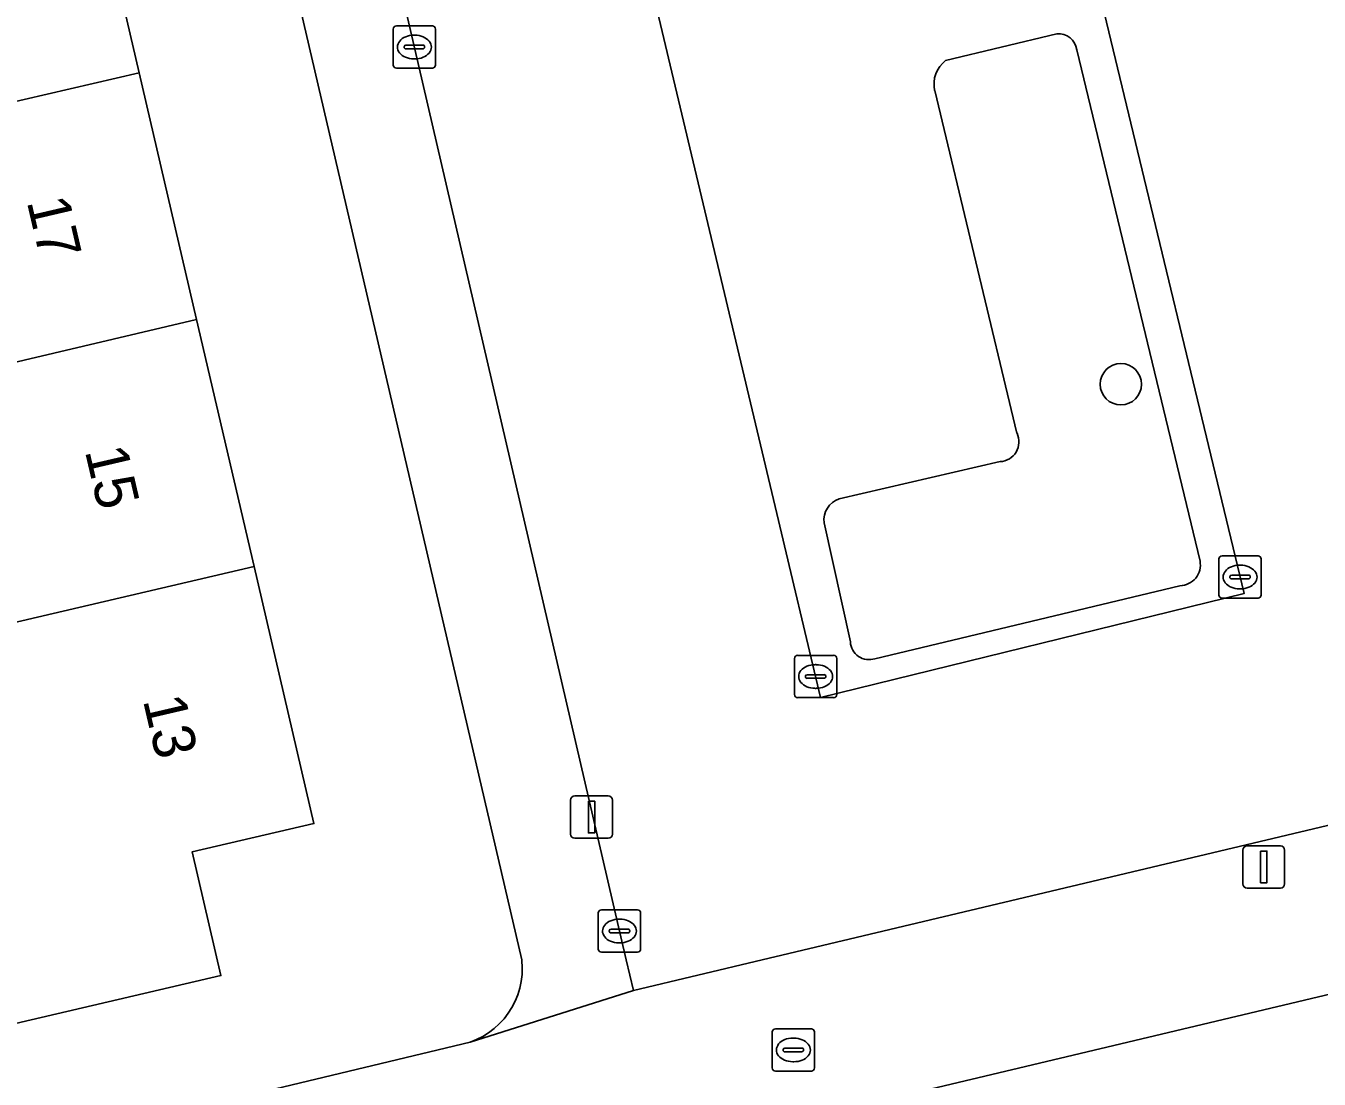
# Model space of a CAD drawing. Extents: x 158031 to 159244, y 380104 to 381214.
# Drawn here: x 158511.52 to 158542.1, y 380747.18 to 380772.08 of the extents above; entities that cross this region are included whole.
import ezdxf

# ---------------------------------------------------------------- set-up
doc = ezdxf.new("R2010")
doc.units = 0
for name, color, linetype in [('IMGEO_Boom', 7, 'Continuous'), ('IMGEO_Erf', 7, 'Continuous'), ('IMGEO_Groenvoorziening', 7, 'Continuous'), ('IMGEO_Kolk', 7, 'Continuous'), ('IMGEO_Lichtmast', 7, 'Continuous'), ('IMGEO_Pand', 7, 'Continuous'), ('IMGEO_Pand_nummerreeks', 7, 'Continuous'), ('IMGEO_Parkeervlak_open', 7, 'Continuous'), ('IMGEO_Rijbaan_lokaal_open', 7, 'Continuous'), ('IMGEO_Rioolput', 7, 'Continuous'), ('IMGEO_Voetpad_open', 7, 'Continuous')]:
    doc.layers.add(name, color=color, linetype=linetype)

msp = doc.modelspace()

# ---------------------------------------------------------------- linework, layer by layer
at = {"layer": 'IMGEO_Boom'}
msp.add_circle((158537.411, 380763.609), 0.489, dxfattribs=at)
at = {"layer": 'IMGEO_Erf'}
for points in [[(158513.376, 380745.986), (158522.019, 380748.055), (158522.172, 380748.116), (158522.319, 380748.19), (158522.458, 380748.277), (158522.589, 380748.376), (158522.711, 380748.487), (158522.823, 380748.607), (158522.923, 380748.738), (158523.011, 380748.877), (158523.087, 380749.023), (158523.149, 380749.175), (158523.197, 380749.332), (158523.231, 380749.493), (158523.251, 380749.657), (158523.255, 380749.821), (158523.246, 380749.985), (158523.244, 380750), (158511.631, 380799.863)], [(158511.474, 380782.644), (158512.835, 380776.803), (158514.193, 380770.97), (158515.552, 380765.137), (158516.911, 380759.304), (158518.328, 380753.222), (158515.445, 380752.551), (158516.126, 380749.629), (158505.929, 380747.254)], [(158545.767, 380750), (158515.725, 380742.86), (158520.628, 380722.152), (158526.203, 380723.472), (158552.37, 380729.668)]]:
    msp.add_lwpolyline(points, dxfattribs=at)
at = {"layer": 'IMGEO_Groenvoorziening'}
for points in [[(158535.895, 380771.89), (158533.268, 380771.262)], [(158539.283, 380759.427), (158536.368, 380771.514)], [(158533.008, 380770.554), (158534.955, 380762.449)], [(158534.556, 380761.78), (158530.749, 380760.899)], [(158530.392, 380760.331), (158531.015, 380757.519)], [(158531.595, 380757.121), (158538.808, 380758.847)]]:
    msp.add_lwpolyline(points, dxfattribs=at)
for centre, radius, start, end in [((158535.941, 380771.463), 0.43, 6.8369, 96.1989), ((158533.689, 380770.706), 0.698, 127.1097, 192.5607), ((158534.533, 380762.247), 0.468, 272.8147, 25.5605), ((158530.922, 380760.394), 0.534, 108.9016, 186.7979), ((158538.803, 380759.336), 0.489, 270.5911, 10.7764), ((158531.456, 380757.54), 0.441, 182.7007, 288.3829)]:
    msp.add_arc(centre, radius, start, end, dxfattribs=at)
at = {"layer": 'IMGEO_Kolk'}
for p, q in [((158520.203, 380771.155), (158520.203, 380772.007)), ((158520.278, 380772.081), (158521.13, 380772.081)), ((158521.204, 380772.007), (158521.204, 380771.155)), ((158520.505, 380771.624), (158520.903, 380771.624)), ((158520.691, 380771.861), (158520.716, 380771.861)), ((158520.462, 380771.575), (158520.462, 380771.587)), ((158520.9, 380771.538), (158520.502, 380771.538)), ((158520.946, 380771.587), (158520.946, 380771.575)), ((158521.13, 380771.081), (158520.278, 380771.081)), ((158520.714, 380771.301), (158520.689, 380771.301)), ((158539.73, 380758.626), (158539.73, 380759.478)), ((158539.805, 380759.552), (158540.657, 380759.552)), ((158540.731, 380759.478), (158540.731, 380758.626)), ((158540.032, 380759.095), (158540.43, 380759.095)), ((158540.218, 380759.332), (158540.243, 380759.332)), ((158539.989, 380759.046), (158539.989, 380759.058)), ((158540.427, 380759.009), (158540.029, 380759.009)), ((158540.241, 380758.772), (158540.216, 380758.772)), ((158540.473, 380759.058), (158540.473, 380759.046)), ((158540.657, 380758.552), (158539.805, 380758.552)), ((158529.692, 380756.274), (158529.692, 380757.126)), ((158529.767, 380757.2), (158530.619, 380757.2)), ((158530.18, 380756.98), (158530.205, 380756.98)), ((158530.693, 380757.126), (158530.693, 380756.274)), ((158529.951, 380756.694), (158529.951, 380756.706)), ((158530.389, 380756.657), (158529.991, 380756.657)), ((158529.994, 380756.743), (158530.392, 380756.743)), ((158530.435, 380756.706), (158530.435, 380756.694)), ((158530.203, 380756.42), (158530.178, 380756.42)), ((158530.619, 380756.2), (158529.767, 380756.2)), ((158525.128, 380751.183), (158525.98, 380751.183)), ((158525.053, 380750.257), (158525.053, 380751.109)), ((158525.541, 380750.963), (158525.566, 380750.963)), ((158526.054, 380751.109), (158526.054, 380750.257)), ((158525.312, 380750.677), (158525.312, 380750.689)), ((158525.75, 380750.64), (158525.352, 380750.64)), ((158525.355, 380750.726), (158525.753, 380750.726)), ((158525.796, 380750.689), (158525.796, 380750.677)), ((158525.564, 380750.403), (158525.539, 380750.403)), ((158525.98, 380750.183), (158525.128, 380750.183))]:
    msp.add_line(p, q, dxfattribs=at)
for points in [[(158520.203, 380771.155), (158520.203, 380772.007)], [(158520.278, 380772.081), (158521.13, 380772.081)], [(158521.204, 380772.007), (158521.204, 380771.155)], [(158521.13, 380771.081), (158520.278, 380771.081)], [(158539.73, 380758.626), (158539.73, 380759.478)], [(158539.805, 380759.552), (158540.657, 380759.552)], [(158540.731, 380759.478), (158540.731, 380758.626)], [(158540.657, 380758.552), (158539.805, 380758.552)], [(158529.692, 380756.274), (158529.692, 380757.126)], [(158529.767, 380757.2), (158530.619, 380757.2)], [(158530.693, 380757.126), (158530.693, 380756.274)], [(158530.619, 380756.2), (158529.767, 380756.2)], [(158525.128, 380751.183), (158525.98, 380751.183)], [(158525.053, 380750.257), (158525.053, 380751.109)], [(158526.054, 380751.109), (158526.054, 380750.257)], [(158525.98, 380750.183), (158525.128, 380750.183)]]:
    msp.add_lwpolyline(points, dxfattribs=at)
for centre, radius, start, end in [((158520.28, 380772.005), 0.0765, 91.552, 178.448), ((158520.28, 380772.005), 0.0765, 91.552, 178.448), ((158521.128, 380772.005), 0.0765, 1.552, 88.448), ((158521.128, 380772.005), 0.0765, 1.552, 88.448), ((158520.502, 380771.584), 0.0403, 85.8775, 175.7526), ((158520.907, 380771.586), 0.0386, 1.7309, 96.639), ((158520.499, 380771.574), 0.0366, 178.938, 274.7102), ((158520.903, 380771.581), 0.043, 264.8664, 352.4533), ((158520.28, 380771.157), 0.0765, 181.552, 268.448), ((158520.28, 380771.157), 0.0765, 181.552, 268.448), ((158521.128, 380771.157), 0.0765, 271.552, 358.448), ((158521.128, 380771.157), 0.0765, 271.552, 358.448), ((158539.807, 380759.476), 0.0765, 91.552, 178.448), ((158539.807, 380759.476), 0.0765, 91.552, 178.448), ((158540.655, 380759.476), 0.0765, 1.552, 88.448), ((158540.655, 380759.476), 0.0765, 1.552, 88.448), ((158540.029, 380759.055), 0.0403, 85.8775, 175.7526), ((158540.434, 380759.057), 0.0386, 1.7309, 96.639), ((158540.026, 380759.045), 0.0366, 178.938, 274.7102), ((158540.43, 380759.052), 0.043, 264.8664, 352.4533), ((158539.807, 380758.628), 0.0765, 181.552, 268.448), ((158539.807, 380758.628), 0.0765, 181.552, 268.448), ((158540.655, 380758.628), 0.0765, 271.552, 358.448), ((158540.655, 380758.628), 0.0765, 271.552, 358.448), ((158529.769, 380757.124), 0.0765, 91.552, 178.448), ((158529.769, 380757.124), 0.0765, 91.552, 178.448), ((158530.617, 380757.124), 0.0765, 1.552, 88.448), ((158530.617, 380757.124), 0.0765, 1.552, 88.448), ((158529.991, 380756.703), 0.0403, 85.8775, 175.7526), ((158529.988, 380756.693), 0.0366, 178.938, 274.7102), ((158530.392, 380756.7), 0.043, 264.8664, 352.4533), ((158530.396, 380756.705), 0.0386, 1.7309, 96.639), ((158529.769, 380756.276), 0.0765, 181.552, 268.448), ((158529.769, 380756.276), 0.0765, 181.552, 268.448), ((158530.617, 380756.276), 0.0765, 271.552, 358.448), ((158530.617, 380756.276), 0.0765, 271.552, 358.448), ((158525.13, 380751.107), 0.0765, 91.552, 178.448), ((158525.13, 380751.107), 0.0765, 91.552, 178.448), ((158525.978, 380751.107), 0.0765, 1.552, 88.448), ((158525.978, 380751.107), 0.0765, 1.552, 88.448), ((158525.352, 380750.686), 0.0403, 85.8775, 175.7526), ((158525.349, 380750.676), 0.0366, 178.938, 274.7102), ((158525.753, 380750.683), 0.043, 264.8664, 352.4533), ((158525.757, 380750.688), 0.0386, 1.7309, 96.639), ((158525.13, 380750.259), 0.0765, 181.552, 268.448), ((158525.13, 380750.259), 0.0765, 181.552, 268.448), ((158525.978, 380750.259), 0.0765, 271.552, 358.448), ((158525.978, 380750.259), 0.0765, 271.552, 358.448)]:
    msp.add_arc(centre, radius, start, end, dxfattribs=at)
for centre, major_axis, ratio, start_param, end_param in [((158520.69, 380771.581), (-0.387, 0.002), 0.722429, 4.712389, 7.853982), ((158520.715, 380771.581), (-0.39, 0.002), 0.717154, 1.570796, 4.712389), ((158540.217, 380759.052), (-0.387, 0.002), 0.722429, 4.712389, 7.853982), ((158540.242, 380759.052), (-0.39, 0.002), 0.717154, 1.570796, 4.712389), ((158530.179, 380756.7), (-0.387, 0.002), 0.722429, 4.712389, 7.853982), ((158530.204, 380756.7), (-0.39, 0.002), 0.717154, 1.570796, 4.712389), ((158525.54, 380750.683), (-0.387, 0.002), 0.722429, 4.712389, 7.853982), ((158525.565, 380750.683), (-0.39, 0.002), 0.717154, 1.570796, 4.712389)]:
    msp.add_ellipse(centre, major_axis=major_axis, ratio=ratio, start_param=start_param, end_param=end_param, dxfattribs=at)
at = {"layer": 'IMGEO_Lichtmast'}
for p, q in [((158524.498, 380753.876), (158525.288, 380753.876)), ((158525.288, 380753.876), (158524.498, 380753.876)), ((158524.398, 380752.976), (158524.398, 380753.776)), ((158524.398, 380753.776), (158524.398, 380752.976)), ((158525.388, 380753.776), (158525.388, 380752.976)), ((158525.388, 380752.976), (158525.388, 380753.776)), ((158525.288, 380752.876), (158524.498, 380752.876)), ((158524.498, 380752.876), (158525.288, 380752.876)), ((158540.395, 380752.698), (158541.185, 380752.698)), ((158541.185, 380752.698), (158540.395, 380752.698)), ((158540.295, 380751.798), (158540.295, 380752.598)), ((158540.295, 380752.598), (158540.295, 380751.798)), ((158541.285, 380752.598), (158541.285, 380751.798)), ((158541.285, 380751.798), (158541.285, 380752.598)), ((158541.185, 380751.698), (158540.395, 380751.698)), ((158540.395, 380751.698), (158541.185, 380751.698))]:
    msp.add_line(p, q, dxfattribs=at)
for points in [[(158524.818, 380753.751), (158524.968, 380753.751), (158524.968, 380753.001), (158524.818, 380753.001), (158524.818, 380753.751)], [(158540.715, 380752.573), (158540.865, 380752.573), (158540.865, 380751.823), (158540.715, 380751.823), (158540.715, 380752.573)]]:
    msp.add_lwpolyline(points, dxfattribs=at)
for centre, start, end in [((158524.498, 380753.776), 90, 180), ((158524.498, 380753.776), 90, 180), ((158525.288, 380753.776), 0, 90), ((158525.288, 380753.776), 360, 90), ((158524.498, 380752.976), 180, 270), ((158524.498, 380752.976), 180, 270), ((158525.288, 380752.976), 270, 0), ((158525.288, 380752.976), 270, 0), ((158540.395, 380752.598), 90, 180), ((158540.395, 380752.598), 90, 180), ((158541.185, 380752.598), 0, 90), ((158541.185, 380752.598), 360, 90), ((158540.395, 380751.798), 180, 270), ((158540.395, 380751.798), 180, 270), ((158541.185, 380751.798), 270, 0), ((158541.185, 380751.798), 270, 0)]:
    msp.add_arc(centre, 0.1, start, end, dxfattribs=at)
at = {"layer": 'IMGEO_Pand'}
for points in [[(158498.735, 380773.552), (158499.179, 380771.688), (158500, 380771.88), (158504.552, 380772.945), (158505.483, 380768.951), (158514.193, 380770.97), (158512.835, 380776.803), (158500, 380773.844)], [(158514.193, 380770.97), (158505.483, 380768.951), (158502.108, 380768.161), (158503.058, 380764.113), (158501.052, 380763.645), (158501.476, 380761.824), (158515.552, 380765.137)], [(158515.552, 380765.137), (158501.476, 380761.824), (158501.889, 380760.051), (158507.306, 380761.313), (158508.246, 380757.275), (158516.911, 380759.304)], [(158516.911, 380759.304), (158508.246, 380757.275), (158506.151, 380756.772), (158505.929, 380747.254), (158516.126, 380749.629), (158515.445, 380752.551), (158518.328, 380753.222)]]:
    msp.add_lwpolyline(points, close=True, dxfattribs=at)
at = {"layer": 'IMGEO_Parkeervlak_open'}
msp.add_lwpolyline([(158533.569, 380786.69), (158523.615, 380784.341), (158529.274, 380760.557), (158530.311, 380756.201), (158540.327, 380758.659), (158537.07, 380772.17)], close=True, dxfattribs=at)
for points in [[(158533.268, 380771.262), (158535.895, 380771.89)], [(158536.368, 380771.514), (158539.283, 380759.427)], [(158534.955, 380762.449), (158533.008, 380770.554)], [(158530.749, 380760.899), (158534.556, 380761.78)], [(158531.015, 380757.519), (158530.392, 380760.331)], [(158538.808, 380758.847), (158531.595, 380757.121)]]:
    msp.add_lwpolyline(points, dxfattribs=at)
for centre, radius, start, end in [((158535.941, 380771.463), 0.43, 6.8369, 96.1989), ((158533.689, 380770.706), 0.698, 127.1097, 192.5607), ((158534.533, 380762.247), 0.468, 272.8147, 25.5605), ((158530.922, 380760.394), 0.534, 108.9016, 186.7979), ((158538.803, 380759.336), 0.489, 270.5911, 10.7764), ((158531.456, 380757.54), 0.441, 182.7007, 288.3829)]:
    msp.add_arc(centre, radius, start, end, dxfattribs=at)
at = {"layer": 'IMGEO_Rijbaan_lokaal_open'}
for points in [[(158541.806, 380778.346), (158538.573, 380791.773), (158538.226, 380793.212), (158538.129, 380793.613), (158535.941, 380793.094), (158520.821, 380789.512), (158516.767, 380788.551), (158525.714, 380750), (158525.882, 380749.276), (158528.927, 380750), (158547.375, 380754.387), (158545.124, 380763.759), (158544.131, 380767.891), (158542.939, 380773.643)], [(158537.07, 380772.17), (158540.327, 380758.659), (158530.311, 380756.201), (158529.274, 380760.557), (158523.615, 380784.341), (158533.569, 380786.69)]]:
    msp.add_lwpolyline(points, close=True, dxfattribs=at)
at = {"layer": 'IMGEO_Rioolput'}
for p, q in [((158529.241, 380748.372), (158530.093, 380748.372)), ((158529.166, 380747.446), (158529.166, 380748.298)), ((158529.654, 380748.152), (158529.679, 380748.152)), ((158530.167, 380748.298), (158530.167, 380747.446)), ((158529.425, 380747.866), (158529.425, 380747.878)), ((158529.863, 380747.829), (158529.465, 380747.829)), ((158529.468, 380747.915), (158529.866, 380747.915)), ((158529.909, 380747.878), (158529.909, 380747.866)), ((158529.677, 380747.592), (158529.652, 380747.592)), ((158530.093, 380747.372), (158529.241, 380747.372))]:
    msp.add_line(p, q, dxfattribs=at)
for points in [[(158529.241, 380748.372), (158530.093, 380748.372)], [(158529.166, 380747.446), (158529.166, 380748.298)], [(158530.167, 380748.298), (158530.167, 380747.446)], [(158530.093, 380747.372), (158529.241, 380747.372)]]:
    msp.add_lwpolyline(points, dxfattribs=at)
for centre, radius, start, end in [((158529.243, 380748.296), 0.0765, 91.552, 178.448), ((158529.243, 380748.296), 0.0765, 91.552, 178.448), ((158530.091, 380748.296), 0.0765, 1.552, 88.448), ((158530.091, 380748.296), 0.0765, 1.552, 88.448), ((158529.465, 380747.875), 0.0403, 85.8775, 175.7526), ((158529.462, 380747.865), 0.0366, 178.938, 274.7102), ((158529.866, 380747.872), 0.043, 264.8664, 352.4533), ((158529.87, 380747.877), 0.0386, 1.7309, 96.639), ((158529.243, 380747.448), 0.0765, 181.552, 268.448), ((158529.243, 380747.448), 0.0765, 181.552, 268.448), ((158530.091, 380747.448), 0.0765, 271.552, 358.448), ((158530.091, 380747.448), 0.0765, 271.552, 358.448)]:
    msp.add_arc(centre, radius, start, end, dxfattribs=at)
for centre, major_axis, ratio, start_param, end_param in [((158529.653, 380747.872), (-0.387, 0.002), 0.722429, 4.712389, 7.853982), ((158529.678, 380747.872), (-0.39, 0.002), 0.717154, 1.570796, 4.712389)]:
    msp.add_ellipse(centre, major_axis=major_axis, ratio=ratio, start_param=start_param, end_param=end_param, dxfattribs=at)
at = {"layer": 'IMGEO_Voetpad_open'}
msp.add_lwpolyline([(158516.767, 380788.551), (158515.561, 380793.744), (158515.274, 380793.677), (158513.72, 380800.306), (158511.631, 380799.863), (158523.244, 380750), (158523.246, 380749.985), (158523.255, 380749.821), (158523.251, 380749.657), (158523.231, 380749.493), (158523.197, 380749.332), (158523.149, 380749.175), (158523.087, 380749.023), (158523.011, 380748.877), (158522.923, 380748.738), (158522.823, 380748.607), (158522.711, 380748.487), (158522.589, 380748.376), (158522.458, 380748.277), (158522.319, 380748.19), (158522.172, 380748.116), (158522.019, 380748.055), (158525.882, 380749.276), (158525.714, 380750)], close=True, dxfattribs=at)
msp.add_lwpolyline([(158464.494, 380730.142), (158468.687, 380731.665), (158468.822, 380731.711), (158468.961, 380731.745), (158500, 380739.122), (158514.382, 380742.54), (158514.435, 380742.553), (158515.725, 380742.86), (158545.767, 380750), (158554.051, 380751.969), (158553.139, 380755.776), (158547.375, 380754.387), (158528.927, 380750), (158525.882, 380749.276), (158522.019, 380748.055), (158513.376, 380745.986), (158501.421, 380743.123), (158500, 380742.783), (158499.62, 380742.692), (158478.792, 380737.705), (158478.748, 380737.696), (158478.584, 380737.674), (158474.565, 380737.039), (158458.956, 380733.307)], dxfattribs=at)

# ---------------------------------------------------------------- texts
at = {"layer": 'IMGEO_Pand_nummerreeks'}
for s, rotation, p in [('17', 283.1148, (158511.533, 380767.932)), ('15', 283.1136, (158512.907, 380762.037)), ('13', 283.1136, (158514.28, 380756.142))]:
    msp.add_text(s, height=1, rotation=rotation, dxfattribs=at).set_placement(p)

doc.saveas('drawing.dxf')
